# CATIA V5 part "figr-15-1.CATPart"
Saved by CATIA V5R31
Part number: Part1
Bounding box of the stored display mesh (mm): x -92.657 to 112.488, y -68.408 to 38.341, z -24 to 61.972
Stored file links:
  D:\PROJECTS\Project 2021\US EDITION\CATIA V5 6R 2021\Resources\Part Files\c15_catia_v5_6r2021_prt\figr-15-1.CATPart
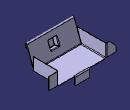
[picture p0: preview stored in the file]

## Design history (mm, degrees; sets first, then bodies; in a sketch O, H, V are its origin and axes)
SheetMetalParameters1: Thickness 1, BendRadius 2, KFactor 0.400515 {= log(min(100,max(20*SheetMetalParameters1.BendRadius,SheetMetalParameters1.Thickness)/SheetMetalParameters1.Thickness))/log(100)/2}, ReliefRadialLength 1, ReliefAxialLength 2, WallPerLength 50, MinimumBendRadius 0
Body1 (main body)
  Sketch1 on xy-plane, origin (0, 0, 0), H (1, 0, 0), V (0, 1, 0)
    line L1 (-62.6567, 37.3409) -> (82.4875, 37.3409)
    line L2 (82.4875, 37.3409) -> (82.4875, -38.1848)
    line L3 (82.4875, -38.1848) -> (-62.6567, -38.1848)
    line L4 (-62.6567, -38.1848) -> (-62.6567, 37.3409)
    horizontal: L1 H, L3 H
    vertical: L2 V, L4 V
  Wall1: Thickness 1, Profile Sketch1, OffsetValue 0
  d_NewWallOnEdge1: NewWallOnEdge_Length 25, NewWallOnEdge_HeightLimitOffset 0, NewWallOnEdge_WidthOffset1 -50, NewWallOnEdge_WidthOffset2 -50, NewWallOnEdge_Angle 90, NewWallOnEdge_BendRadiusValue 2 {= SheetMetalParameters1.BendRadius}, NewWallOnEdge_BendTable SheetMetalParameters1, NewWallOnEdge_Edge edge [face of Wall1 | face of Wall1], NewWallOnEdge_GapValue 0, KFacteur 0.400515 {= log(min(100,max(20*d_NewWallOnEdge1.Radius,SheetMetalParameters1.Thickness)/SheetMetalParameters1.Thickness))/log(100)/2}
  d_NewWallOnEdge2: NewWallOnEdge_Length 40, NewWallOnEdge_HeightLimitOffset 0, NewWallOnEdge_WidthOffset1 0, NewWallOnEdge_WidthOffset2 0, NewWallOnEdge_Angle 90, NewWallOnEdge_BendRadiusValue 2 {= SheetMetalParameters1.BendRadius}, NewWallOnEdge_BendTable SheetMetalParameters1, NewWallOnEdge_Edge edge [face of Wall1 | face of Wall1], NewWallOnEdge_GapValue 0, KFacteur 0.400515 {= log(min(100,max(20*d_NewWallOnEdge2.Radius,SheetMetalParameters1.Thickness)/SheetMetalParameters1.Thickness))/log(100)/2}
  d_NewWallOnEdge3: NewWallOnEdge_Length 30, NewWallOnEdge_HeightLimitOffset 0, NewWallOnEdge_WidthOffset1 0, NewWallOnEdge_WidthOffset2 0, NewWallOnEdge_Angle 90, NewWallOnEdge_BendRadiusValue 2 {= SheetMetalParameters1.BendRadius}, NewWallOnEdge_BendTable SheetMetalParameters1, NewWallOnEdge_Edge edge [face of d_NewWallOnEdge2 | face of d_NewWallOnEdge2], NewWallOnEdge_GapValue 0, KFacteur 0.400515 {= log(min(100,max(20*d_NewWallOnEdge3.Radius,SheetMetalParameters1.Thickness)/SheetMetalParameters1.Thickness))/log(100)/2}
  d_NewWallOnEdge4: NewWallOnEdge_Length 60, NewWallOnEdge_HeightLimitOffset 0, NewWallOnEdge_WidthOffset1 0, NewWallOnEdge_WidthOffset2 0, NewWallOnEdge_Angle 110, NewWallOnEdge_BendRadiusValue 2 {= SheetMetalParameters1.BendRadius}, NewWallOnEdge_BendTable SheetMetalParameters1, NewWallOnEdge_Edge edge [face of Wall1 | face of Wall1], NewWallOnEdge_GapValue 0, KFacteur 0.400515 {= log(min(100,max(20*d_NewWallOnEdge4.Radius,SheetMetalParameters1.Thickness)/SheetMetalParameters1.Thickness))/log(100)/2}
  Flange1: Angle 90, Length 10, Radius 2 {= SheetMetalParameters1.BendRadius}, KFacteur 0.400515 {= log(min(100,max(20*Flange1.Radius,SheetMetalParameters1.Thickness)/SheetMetalParameters1.Thickness))/log(100)/2}, Guide edge [face of d_NewWallOnEdge4 | face of d_NewWallOnEdge4]
  d_NewWallOnEdge5: NewWallOnEdge_Length 40, NewWallOnEdge_HeightLimitOffset 0, NewWallOnEdge_WidthLimit2 face of d_NewWallOnEdge4, NewWallOnEdge_WidthOffset1 0, NewWallOnEdge_WidthOffset2 -2, NewWallOnEdge_Angle 90, NewWallOnEdge_WithBend true, NewWallOnEdge_BendRadiusValue 2 {= SheetMetalParameters1.BendRadius}, NewWallOnEdge_BendTable SheetMetalParameters1, NewWallOnEdge_Edge edge [face of Wall1 | face of Wall1], NewWallOnEdge_GapValue 0, KFacteur 0.400515 {= log(min(100,max(20*d_NewWallOnEdge5.Radius,SheetMetalParameters1.Thickness)/SheetMetalParameters1.Thickness))/log(100)/2}
  d_NewWallOnEdge6: NewWallOnEdge_Length 30, NewWallOnEdge_HeightLimitOffset 0, NewWallOnEdge_WidthOffset1 0, NewWallOnEdge_WidthOffset2 0, NewWallOnEdge_Angle 90, NewWallOnEdge_BendRadiusValue 2 {= SheetMetalParameters1.BendRadius}, NewWallOnEdge_BendTable SheetMetalParameters1, NewWallOnEdge_Edge edge [face of d_NewWallOnEdge5 | face of d_NewWallOnEdge5], NewWallOnEdge_GapValue 0, KFacteur 0.400515 {= log(min(100,max(20*d_NewWallOnEdge6.Radius,SheetMetalParameters1.Thickness)/SheetMetalParameters1.Thickness))/log(100)/2}
  Chamfer1: ChamferAngle 45, ChamferLength1 20, ChamferLength2 0.5, ChamferPropagation 1, ChamferReverse false, ChamferType 1, CornerChamferEdges edge [face of d_NewWallOnEdge6 | face of d_NewWallOnEdge6]
  Corner1: CornerRadius 3, CornerChamferEdges (edge [face of d_NewWallOnEdge1 | face of d_NewWallOnEdge1]; edge [face of d_NewWallOnEdge1 | face of d_NewWallOnEdge1])
  Sketch2 on face of d_NewWallOnEdge4, origin (8.9154, -38.1848, 1), H (1, 0, 0), V (0, -0.342, 0.9397)
    line L1 (-12.2908, 45.4061) -> (12.3784, 45.4061)
    line L2 (12.3784, 45.4061) -> (12.3784, 21.719)
    line L3 (12.3784, 21.719) -> (-12.2908, 21.719)
    line L4 (-12.2908, 21.719) -> (-12.2908, 45.4061)
    horizontal: L1 H, L3 H
    vertical: L2 V, L4 V
  d_Stamp1: NewRoot_AttribNormalisation "No Standard", Stamp_FilletRadius 1, Stamp_IntersectFilletRadius 2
